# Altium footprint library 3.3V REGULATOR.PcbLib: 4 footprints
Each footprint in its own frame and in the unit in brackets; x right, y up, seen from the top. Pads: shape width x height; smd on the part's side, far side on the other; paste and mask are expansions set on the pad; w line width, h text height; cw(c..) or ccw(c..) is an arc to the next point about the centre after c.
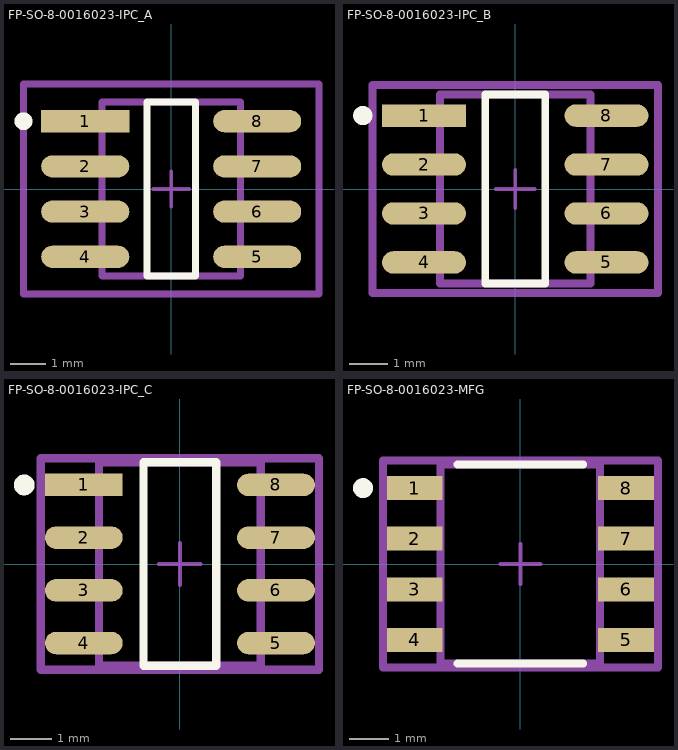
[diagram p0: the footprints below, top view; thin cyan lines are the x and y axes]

## FP-SO-8-0016023-IPC_A [mil]
pads (8):
  rect 97.4x24.49 smd paste+0 mask+0: 1(-95.12,75)
  rrect100% 97.4x24.49 smd paste+0 mask+0: 2(-95.12,25) 3(-95.12,-25) 4(-95.12,-75) 5(95.12,-75) 6(95.12,-25) 7(95.12,25) 8(95.12,75)
Top Overlay:
  circle w9.84: c-163.51,75 r4.92
  lines w7.87: -26.73,-96.46 26.73,-96.46 26.73,96.46 -26.73,96.46 -26.73,-96.46
Top Assembly:
  lines w7.87: -163.51,-116.14 163.51,-116.14 163.51,116.14 -163.51,116.14 -163.51,-116.14
  text ".Designator" at 0,7.39 h39.37
Top 3D Body:
  lines w7.87: -76.77,-96.46 76.77,-96.46 76.77,96.46 -76.77,96.46 -76.77,-96.46
Top Courtyard:
  lines w7.87: -163.51,-116.14 163.51,-116.14 163.51,116.14 -163.51,116.14 -163.51,-116.14
Top Component Center:
  lines w3.94: -19.68,0 19.68,0 ; 0,-19.68 0,19.68
3D body "IC_STMicroelectronics_LD1117D33TR_eec.STEP": height 10, standoff 0, extent -163.51,-116.14 163.51,116.14

## FP-SO-8-0016023-IPC_B [mil]
pads (8):
  rect 85.59x22.92 smd paste+0 mask+0: 1(-93.15,75)
  rrect100% 85.59x22.92 smd paste+0 mask+0: 2(-93.15,25) 3(-93.15,-25) 4(-93.15,-75) 5(93.15,-75) 6(93.15,-25) 7(93.15,25) 8(93.15,75)
Top Overlay:
  circle w9.84: c-155.63,75 r4.92
  lines w7.87: -30.67,-96.46 30.67,-96.46 30.67,96.46 -30.67,96.46 -30.67,-96.46
Top Assembly:
  lines w7.87: -145.79,-106.3 145.79,-106.3 145.79,106.3 -145.79,106.3 -145.79,-106.3
  text ".Designator" at 0,7.39 h39.37
Top 3D Body:
  lines w7.87: -76.77,-96.46 76.77,-96.46 76.77,96.46 -76.77,96.46 -76.77,-96.46
Top Courtyard:
  lines w7.87: -145.79,-106.3 145.79,-106.3 145.79,106.3 -145.79,106.3 -145.79,-106.3
Top Component Center:
  lines w3.94: -19.68,0 19.68,0 ; 0,-19.68 0,19.68
3D body "IC_STMicroelectronics_LD1117D33TR_eec.STEP": height 10, standoff 0, extent -145.79,-106.3 145.79,106.3

## FP-SO-8-0016023-IPC_C [mil]
pads (8):
  rect 73.78x21.34 smd paste+0 mask+0: 1(-91.18,75)
  rrect100% 73.78x21.34 smd paste+0 mask+0: 2(-91.18,25) 3(-91.18,-25) 4(-91.18,-75) 5(91.18,-75) 6(91.18,-25) 7(91.18,25) 8(91.18,75)
Top Overlay:
  circle w9.84: c-147.76,75 r4.92
  lines w7.87: -34.61,-96.46 34.61,-96.46 34.61,96.46 -34.61,96.46 -34.61,-96.46
Top Assembly:
  lines w7.87: -132.01,-100.39 132.01,-100.39 132.01,100.39 -132.01,100.39 -132.01,-100.39
  text ".Designator" at 0,7.39 h39.37
Top 3D Body:
  lines w7.87: -76.77,-96.46 76.77,-96.46 76.77,96.46 -76.77,96.46 -76.77,-96.46
Top Courtyard:
  lines w7.87: -132.01,-100.39 132.01,-100.39 132.01,100.39 -132.01,100.39 -132.01,-100.39
Top Component Center:
  lines w3.94: -19.68,0 19.68,0 ; 0,-19.68 0,19.68
3D body "IC_STMicroelectronics_LD1117D33TR_eec.STEP": height 10, standoff 0, extent -132.01,-100.39 132.01,100.39

## FP-SO-8-0016023-MFG [mm]
pads (8):
  rect 1.4x0.6 smd paste+0 mask+0: 1(-2.65,1.905) 2(-2.65,0.635) 3(-2.65,-0.635) 4(-2.65,-1.905) 5(2.65,-1.905) 6(2.65,-0.635) 7(2.65,0.635) 8(2.65,1.905)
Top Overlay:
  circle w0.25: c-3.95,1.905 r0.125
  lines w0.2: -1.575,-2.5 1.575,-2.5 ; -1.575,2.5 1.575,2.5
Top Assembly:
  lines w0.2: -3.45,-2.6 3.45,-2.6 3.45,2.6 -3.45,2.6 -3.45,-2.6
  text ".Designator" at 0,0.188 h1
Top 3D Body:
  lines w0.2: -2,-2.5 2,-2.5 2,2.5 -2,2.5 -2,-2.5
Top Courtyard:
  lines w0.2: -3.45,-2.6 3.45,-2.6 3.45,2.6 -3.45,2.6 -3.45,-2.6
Top Component Center:
  lines w0.1: -0.5,0 0.5,0 ; 0,-0.5 0,0.5
3D body "IC_STMicroelectronics_LD1117D33TR_eec.STEP": height 0.25, standoff 0, extent -3.45,-2.6 3.45,2.6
